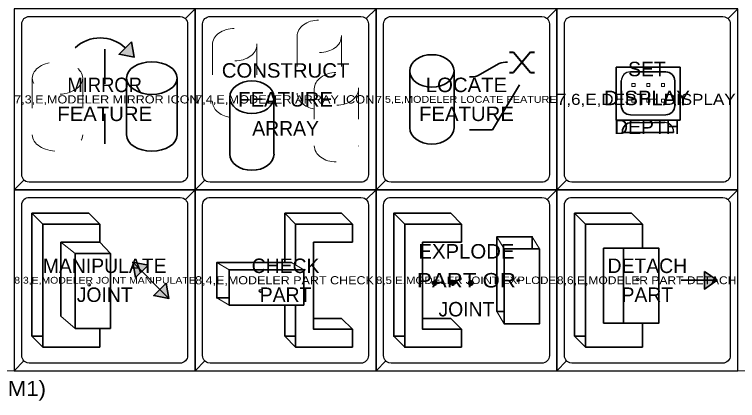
# Model space of a CAD drawing. Extents: x 95909.2 to 95923.3, y 90965 to 90971.2.
# Drawn here: x 95910.988 to 95913.386, y 90966.261 to 90967.542 of the extents above; entities that cross this region are included whole.
import ezdxf
from ezdxf.enums import TextEntityAlignment as Align

# ---------------------------------------------------------------- set-up
doc = ezdxf.new("R2010")
doc.units = 0
doc.header["$LTSCALE"] = 0.019
doc.header["$PDMODE"] = 32
doc.header["$PDSIZE"] = 0.0095
doc.linetypes.add('LONG_DASH_SHORT_DASH', pattern=[9.9, 6, -1.2, 1.5, -1.2])
doc.linetypes.add('MEDIUM_DASHED', pattern=[4.5, 3, -1.5])
for name, color, linetype, lineweight in [('1', 7, 'Continuous', 25), ('10', 7, 'Continuous', 13), ('2', 7, 'Continuous', 25), ('3', 7, 'Continuous', 25), ('4', 7, 'Continuous', 25), ('6', 7, 'Continuous', 13), ('7', 7, 'Continuous', 35)]:
    doc.layers.add(name, color=color, linetype=linetype, lineweight=lineweight)
doc.layers.add('5', color=7, linetype='Continuous')
doc.layers.add('63', color=7, linetype='Continuous')

msp = doc.modelspace()

# ---------------------------------------------------------------- hatches: boundary and pattern name
at = {"layer": '6'}
for points in [[(95911.3759, 90967.4511), (95911.385, 90967.4006), (95911.3346, 90967.4101)], [(95911.3893, 90966.6696), (95911.3799, 90966.7202), (95911.4305, 90966.7108)], [(95913.2761, 90966.6893), (95913.3184, 90966.6603), (95913.2761, 90966.6311)], [(95911.4905, 90966.6508), (95911.4998, 90966.6003), (95911.4493, 90966.6096)], [(95912.3813, 90966.65733, 1), (95912.3813, 90966.64533, 1)], [(95912.44103, 90966.65733, 1), (95912.44103, 90966.64533, 1)], [(95912.5013, 90966.65733, 1), (95912.5013, 90966.64533, 1)]]:
    msp.add_hatch(color=256, dxfattribs=at).paths.add_polyline_path(points)

# ---------------------------------------------------------------- linework, layer by layer
at = {"layer": '1'}
for points in [[(95910.9868, 90966.9603), (95911.5868, 90966.9603), (95911.5868, 90967.5603), (95910.9868, 90967.5603)], [(95911.5868, 90966.9603), (95912.1868, 90966.9603), (95912.1868, 90967.5603), (95911.5868, 90967.5603)], [(95912.1868, 90966.9603), (95912.7868, 90966.9603), (95912.7868, 90967.5603), (95912.1868, 90967.5603)], [(95912.7868, 90966.9603), (95913.3868, 90966.9603), (95913.3868, 90967.5603), (95912.7868, 90967.5603)], [(95910.9868, 90966.3603), (95911.5868, 90966.3603), (95911.5868, 90966.9603), (95910.9868, 90966.9603)], [(95911.5868, 90966.3603), (95912.1868, 90966.3603), (95912.1868, 90966.9603), (95911.5868, 90966.9603)], [(95912.1868, 90966.3603), (95912.7868, 90966.3603), (95912.7868, 90966.9603), (95912.1868, 90966.9603)], [(95912.7868, 90966.3603), (95913.3868, 90966.3603), (95913.3868, 90966.9603), (95912.7868, 90966.9603)]]:
    msp.add_lwpolyline(points, close=True, dxfattribs=at)
at = {"layer": '10'}
msp.add_lwpolyline([(95909.7868, 90971.1603), (95915.7868, 90971.1603), (95915.7868, 90966.3603), (95909.7868, 90966.3603)], close=True, dxfattribs=at)
at = {"layer": '2'}
for points in [[(95910.9868, 90966.9603), (95911.5868, 90966.9603), (95911.5868, 90967.5603), (95910.9868, 90967.5603)], [(95911.5868, 90966.9603), (95912.1868, 90966.9603), (95912.1868, 90967.5603), (95911.5868, 90967.5603)], [(95912.1868, 90966.9603), (95912.7868, 90966.9603), (95912.7868, 90967.5603), (95912.1868, 90967.5603)], [(95912.7868, 90966.9603), (95913.3868, 90966.9603), (95913.3868, 90967.5603), (95912.7868, 90967.5603)], [(95910.9868, 90966.3603), (95911.5868, 90966.3603), (95911.5868, 90966.9603), (95910.9868, 90966.9603)], [(95911.5868, 90966.3603), (95912.1868, 90966.3603), (95912.1868, 90966.9603), (95911.5868, 90966.9603)], [(95912.1868, 90966.3603), (95912.7868, 90966.3603), (95912.7868, 90966.9603), (95912.1868, 90966.9603)], [(95912.7868, 90966.3603), (95913.3868, 90966.3603), (95913.3868, 90966.9603), (95912.7868, 90966.9603)]]:
    msp.add_lwpolyline(points, close=True, dxfattribs=at)
at = {"layer": '3'}
for points in [[(95911.5868, 90967.5603), (95910.9868, 90967.5603), (95910.9868, 90966.9603), (95911.0191, 90966.9926), (95911.016, 90966.9964), (95911.0137, 90967.0007), (95911.0123, 90967.0054), (95911.0118, 90967.0103), (95911.0118, 90967.5103), (95911.0123, 90967.5152), (95911.0137, 90967.5199), (95911.016, 90967.5242), (95911.0191, 90967.528), (95911.0191, 90967.528), (95911.0229, 90967.5311), (95911.0272, 90967.5334), (95911.0319, 90967.5348), (95911.0368, 90967.5353), (95911.5368, 90967.5353), (95911.5441, 90967.5342), (95911.5486, 90967.5323), (95911.5527, 90967.5296), (95911.5545, 90967.528)], [(95912.1868, 90967.5603), (95911.5868, 90967.5603), (95911.5868, 90966.9603), (95911.6191, 90966.9926), (95911.616, 90966.9964), (95911.6137, 90967.0007), (95911.6123, 90967.0054), (95911.6118, 90967.0103), (95911.6118, 90967.5103), (95911.6123, 90967.5152), (95911.6137, 90967.5199), (95911.616, 90967.5242), (95911.6191, 90967.528), (95911.6191, 90967.528), (95911.6229, 90967.5311), (95911.6272, 90967.5334), (95911.6319, 90967.5348), (95911.6368, 90967.5353), (95912.1368, 90967.5353), (95912.1441, 90967.5342), (95912.1486, 90967.5323), (95912.1527, 90967.5296), (95912.1545, 90967.528)], [(95912.7868, 90967.5603), (95912.1868, 90967.5603), (95912.1868, 90966.9603), (95912.2191, 90966.9926), (95912.216, 90966.9964), (95912.2137, 90967.0007), (95912.2123, 90967.0054), (95912.2118, 90967.0103), (95912.2118, 90967.5103), (95912.2123, 90967.5152), (95912.2137, 90967.5199), (95912.216, 90967.5242), (95912.2191, 90967.528), (95912.2191, 90967.528), (95912.2229, 90967.5311), (95912.2272, 90967.5334), (95912.2319, 90967.5348), (95912.2368, 90967.5353), (95912.7368, 90967.5353), (95912.7441, 90967.5342), (95912.7486, 90967.5323), (95912.7527, 90967.5296), (95912.7545, 90967.528)], [(95913.3868, 90967.5603), (95912.7868, 90967.5603), (95912.7868, 90966.9603), (95912.8191, 90966.9926), (95912.816, 90966.9964), (95912.8137, 90967.0007), (95912.8123, 90967.0054), (95912.8118, 90967.0103), (95912.8118, 90967.5103), (95912.8123, 90967.5152), (95912.8137, 90967.5199), (95912.816, 90967.5242), (95912.8191, 90967.528), (95912.8191, 90967.528), (95912.8229, 90967.5311), (95912.8272, 90967.5334), (95912.8319, 90967.5348), (95912.8368, 90967.5353), (95913.3368, 90967.5353), (95913.3441, 90967.5342), (95913.3486, 90967.5323), (95913.3527, 90967.5296), (95913.3545, 90967.528)], [(95911.5868, 90966.9603), (95910.9868, 90966.9603), (95910.9868, 90966.3603), (95911.0191, 90966.3926), (95911.016, 90966.3964), (95911.0137, 90966.4007), (95911.0123, 90966.4054), (95911.0118, 90966.4103), (95911.0118, 90966.9103), (95911.0123, 90966.9152), (95911.0137, 90966.9199), (95911.016, 90966.9242), (95911.0191, 90966.928), (95911.0191, 90966.928), (95911.0229, 90966.9311), (95911.0272, 90966.9334), (95911.0319, 90966.9348), (95911.0368, 90966.9353), (95911.5368, 90966.9353), (95911.5441, 90966.9342), (95911.5486, 90966.9323), (95911.5527, 90966.9296), (95911.5545, 90966.928)], [(95912.1868, 90966.9603), (95911.5868, 90966.9603), (95911.5868, 90966.3603), (95911.6191, 90966.3926), (95911.616, 90966.3964), (95911.6137, 90966.4007), (95911.6123, 90966.4054), (95911.6118, 90966.4103), (95911.6118, 90966.9103), (95911.6123, 90966.9152), (95911.6137, 90966.9199), (95911.616, 90966.9242), (95911.6191, 90966.928), (95911.6191, 90966.928), (95911.6229, 90966.9311), (95911.6272, 90966.9334), (95911.6319, 90966.9348), (95911.6368, 90966.9353), (95912.1368, 90966.9353), (95912.1441, 90966.9342), (95912.1486, 90966.9323), (95912.1527, 90966.9296), (95912.1545, 90966.928)], [(95912.7868, 90966.9603), (95912.1868, 90966.9603), (95912.1868, 90966.3603), (95912.2191, 90966.3926), (95912.216, 90966.3964), (95912.2137, 90966.4007), (95912.2123, 90966.4054), (95912.2118, 90966.4103), (95912.2118, 90966.9103), (95912.2123, 90966.9152), (95912.2137, 90966.9199), (95912.216, 90966.9242), (95912.2191, 90966.928), (95912.2191, 90966.928), (95912.2229, 90966.9311), (95912.2272, 90966.9334), (95912.2319, 90966.9348), (95912.2368, 90966.9353), (95912.7368, 90966.9353), (95912.7441, 90966.9342), (95912.7486, 90966.9323), (95912.7527, 90966.9296), (95912.7545, 90966.928)], [(95913.3868, 90966.9603), (95912.7868, 90966.9603), (95912.7868, 90966.3603), (95912.8191, 90966.3926), (95912.816, 90966.3964), (95912.8137, 90966.4007), (95912.8123, 90966.4054), (95912.8118, 90966.4103), (95912.8118, 90966.9103), (95912.8123, 90966.9152), (95912.8137, 90966.9199), (95912.816, 90966.9242), (95912.8191, 90966.928), (95912.8191, 90966.928), (95912.8229, 90966.9311), (95912.8272, 90966.9334), (95912.8319, 90966.9348), (95912.8368, 90966.9353), (95913.3368, 90966.9353), (95913.3441, 90966.9342), (95913.3486, 90966.9323), (95913.3527, 90966.9296), (95913.3545, 90966.928)]]:
    msp.add_lwpolyline(points, close=True, dxfattribs=at)
at = {"layer": '4'}
for points in [[(95910.9868, 90966.9603), (95911.5868, 90966.9603), (95911.5868, 90967.5603), (95911.5545, 90967.528), (95911.5576, 90967.5242), (95911.5599, 90967.5199), (95911.5613, 90967.5152), (95911.5618, 90967.5103), (95911.5618, 90967.0103), (95911.5613, 90967.0054), (95911.5599, 90967.0007), (95911.5576, 90966.9964), (95911.5545, 90966.9926), (95911.5545, 90966.9926), (95911.5507, 90966.9895), (95911.5464, 90966.9872), (95911.5417, 90966.9858), (95911.5368, 90966.9853), (95911.0368, 90966.9853), (95911.0295, 90966.9864), (95911.025, 90966.9883), (95911.0209, 90966.991), (95911.0191, 90966.9926)], [(95911.5868, 90966.9603), (95912.1868, 90966.9603), (95912.1868, 90967.5603), (95912.1545, 90967.528), (95912.1576, 90967.5242), (95912.1599, 90967.5199), (95912.1613, 90967.5152), (95912.1618, 90967.5103), (95912.1618, 90967.0103), (95912.1613, 90967.0054), (95912.1599, 90967.0007), (95912.1576, 90966.9964), (95912.1545, 90966.9926), (95912.1545, 90966.9926), (95912.1507, 90966.9895), (95912.1464, 90966.9872), (95912.1417, 90966.9858), (95912.1368, 90966.9853), (95911.6368, 90966.9853), (95911.6295, 90966.9864), (95911.625, 90966.9883), (95911.6209, 90966.991), (95911.6191, 90966.9926)], [(95912.1868, 90966.9603), (95912.7868, 90966.9603), (95912.7868, 90967.5603), (95912.7545, 90967.528), (95912.7576, 90967.5242), (95912.7599, 90967.5199), (95912.7613, 90967.5152), (95912.7618, 90967.5103), (95912.7618, 90967.0103), (95912.7613, 90967.0054), (95912.7599, 90967.0007), (95912.7576, 90966.9964), (95912.7545, 90966.9926), (95912.7545, 90966.9926), (95912.7507, 90966.9895), (95912.7464, 90966.9872), (95912.7417, 90966.9858), (95912.7368, 90966.9853), (95912.2368, 90966.9853), (95912.2295, 90966.9864), (95912.225, 90966.9883), (95912.2209, 90966.991), (95912.2191, 90966.9926)], [(95912.7868, 90966.9603), (95913.3868, 90966.9603), (95913.3868, 90967.5603), (95913.3545, 90967.528), (95913.3576, 90967.5242), (95913.3599, 90967.5199), (95913.3613, 90967.5152), (95913.3618, 90967.5103), (95913.3618, 90967.0103), (95913.3613, 90967.0054), (95913.3599, 90967.0007), (95913.3576, 90966.9964), (95913.3545, 90966.9926), (95913.3545, 90966.9926), (95913.3507, 90966.9895), (95913.3464, 90966.9872), (95913.3417, 90966.9858), (95913.3368, 90966.9853), (95912.8368, 90966.9853), (95912.8295, 90966.9864), (95912.825, 90966.9883), (95912.8209, 90966.991), (95912.8191, 90966.9926)], [(95910.9868, 90966.3603), (95911.5868, 90966.3603), (95911.5868, 90966.9603), (95911.5545, 90966.928), (95911.5576, 90966.9242), (95911.5599, 90966.9199), (95911.5613, 90966.9152), (95911.5618, 90966.9103), (95911.5618, 90966.4103), (95911.5613, 90966.4054), (95911.5599, 90966.4007), (95911.5576, 90966.3964), (95911.5545, 90966.3926), (95911.5545, 90966.3926), (95911.5507, 90966.3895), (95911.5464, 90966.3872), (95911.5417, 90966.3858), (95911.5368, 90966.3853), (95911.0368, 90966.3853), (95911.0295, 90966.3864), (95911.025, 90966.3883), (95911.0209, 90966.391), (95911.0191, 90966.3926)], [(95911.5868, 90966.3603), (95912.1868, 90966.3603), (95912.1868, 90966.9603), (95912.1545, 90966.928), (95912.1576, 90966.9242), (95912.1599, 90966.9199), (95912.1613, 90966.9152), (95912.1618, 90966.9103), (95912.1618, 90966.4103), (95912.1613, 90966.4054), (95912.1599, 90966.4007), (95912.1576, 90966.3964), (95912.1545, 90966.3926), (95912.1545, 90966.3926), (95912.1507, 90966.3895), (95912.1464, 90966.3872), (95912.1417, 90966.3858), (95912.1368, 90966.3853), (95911.6368, 90966.3853), (95911.6295, 90966.3864), (95911.625, 90966.3883), (95911.6209, 90966.391), (95911.6191, 90966.3926)], [(95912.1868, 90966.3603), (95912.7868, 90966.3603), (95912.7868, 90966.9603), (95912.7545, 90966.928), (95912.7576, 90966.9242), (95912.7599, 90966.9199), (95912.7613, 90966.9152), (95912.7618, 90966.9103), (95912.7618, 90966.4103), (95912.7613, 90966.4054), (95912.7599, 90966.4007), (95912.7576, 90966.3964), (95912.7545, 90966.3926), (95912.7545, 90966.3926), (95912.7507, 90966.3895), (95912.7464, 90966.3872), (95912.7417, 90966.3858), (95912.7368, 90966.3853), (95912.2368, 90966.3853), (95912.2295, 90966.3864), (95912.225, 90966.3883), (95912.2209, 90966.391), (95912.2191, 90966.3926)], [(95912.7868, 90966.3603), (95913.3868, 90966.3603), (95913.3868, 90966.9603), (95913.3545, 90966.928), (95913.3576, 90966.9242), (95913.3599, 90966.9199), (95913.3613, 90966.9152), (95913.3618, 90966.9103), (95913.3618, 90966.4103), (95913.3613, 90966.4054), (95913.3599, 90966.4007), (95913.3576, 90966.3964), (95913.3545, 90966.3926), (95913.3545, 90966.3926), (95913.3507, 90966.3895), (95913.3464, 90966.3872), (95913.3417, 90966.3858), (95913.3368, 90966.3853), (95912.8368, 90966.3853), (95912.8295, 90966.3864), (95912.825, 90966.3883), (95912.8209, 90966.391), (95912.8191, 90966.3926)]]:
    msp.add_lwpolyline(points, close=True, dxfattribs=at)
at = {"layer": '6', "linetype": 'MEDIUM_DASHED'}
for p, q in [((95911.9251, 90967.4693), (95911.9251, 90967.2809)), ((95912.0721, 90967.4693), (95912.0721, 90967.3477)), ((95911.6444, 90967.4416), (95911.6444, 90967.2532)), ((95911.7914, 90967.4416), (95911.7914, 90967.3201)), ((95911.0468, 90967.3307), (95911.0468, 90967.1423)), ((95911.2139, 90967.3307), (95911.2139, 90967.1423)), ((95911.9821, 90967.2951), (95911.9821, 90967.1066)), ((95912.1291, 90967.2951), (95912.1291, 90967.1066))]:
    msp.add_line(p, q, dxfattribs=at)
at = {"layer": '6', "linetype": 'LONG_DASH_SHORT_DASH', "lineweight": 35}
msp.add_line((95911.2868, 90967.4263), (95911.2868, 90967.0683), dxfattribs=at)
at = {"layer": '6', "lineweight": 40}
for p, q in [((95912.6296, 90967.4172), (95912.6431, 90967.4172)), ((95912.6431, 90967.4172), (95912.6988, 90967.3496)), ((95912.6988, 90967.4172), (95912.6431, 90967.3496)), ((95912.6988, 90967.4172), (95912.7122, 90967.4172)), ((95912.6296, 90967.3496), (95912.6431, 90967.3496)), ((95912.6988, 90967.3496), (95912.7122, 90967.3496))]:
    msp.add_line(p, q, dxfattribs=at)
at = {"layer": '6', "lineweight": 35}
for p, q in [((95912.5239, 90967.3388), (95912.5956, 90967.3793)), ((95912.2985, 90967.3545), (95912.2985, 90967.166)), ((95912.4455, 90967.3545), (95912.4455, 90967.166)), ((95913.1479, 90967.3513), (95913.0304, 90967.3513)), ((95911.3597, 90967.3307), (95911.3597, 90967.1423)), ((95911.5268, 90967.3307), (95911.5268, 90967.1423)), ((95913.0004, 90967.3213), (95913.0004, 90967.2389)), ((95913.1779, 90967.2389), (95913.1779, 90967.3213)), ((95912.5731, 90967.159), (95912.6624, 90967.3086)), ((95911.7014, 90967.2674), (95911.7014, 90967.0789)), ((95911.8484, 90967.2674), (95911.8484, 90967.0789)), ((95912.5731, 90967.159), (95912.4966, 90967.159)), ((95913.174, 90967.1504), (95913.0043, 90967.1504)), ((95912.0727, 90966.8824), (95911.8839, 90966.8824)), ((95911.8839, 90966.8824), (95911.8839, 90966.7188)), ((95911.2707, 90966.846), (95911.2707, 90966.7866)), ((95912.1091, 90966.846), (95911.9202, 90966.846)), ((95911.9202, 90966.846), (95911.9202, 90966.7112)), ((95912.1091, 90966.846), (95912.1091, 90966.7866)), ((95912.4707, 90966.846), (95912.4707, 90966.7866)), ((95913.0707, 90966.846), (95913.0707, 90966.7662)), ((95913.0079, 90966.7662), (95912.9414, 90966.7662)), ((95911.4998, 90966.6003), (95911.3799, 90966.7202)), ((95913.199, 90966.6603), (95913.3184, 90966.6603)), ((95911.8839, 90966.5781), (95911.8839, 90966.4744)), ((95911.9202, 90966.5781), (95911.9202, 90966.438)), ((95912.5879, 90966.5566), (95912.6114, 90966.5566)), ((95911.9797, 90966.5339), (95912.0727, 90966.5339)), ((95912.3414, 90966.5339), (95912.4345, 90966.5339)), ((95911.2707, 90966.438), (95911.2707, 90966.5003)), ((95913.0707, 90966.438), (95913.0707, 90966.518)), ((95912.1091, 90966.438), (95912.1091, 90966.4976)), ((95912.4707, 90966.438), (95912.4707, 90966.4976)), ((95911.8839, 90966.4744), (95911.9202, 90966.4744)), ((95911.9202, 90966.438), (95912.1091, 90966.438))]:
    msp.add_line(p, q, dxfattribs=at)
at = {"layer": '6', "lineweight": 25}
for p, q in [((95913.0304, 90967.2089), (95913.1479, 90967.2089)), ((95913.0343, 90967.1835), (95913.144, 90967.1835)), ((95913.0043, 90967.1504), (95913.0043, 90967.1535)), ((95913.174, 90967.1535), (95913.174, 90967.1504))]:
    msp.add_line(p, q, dxfattribs=at)
at = {"layer": '6'}
for p, q in [((95911.0819, 90966.846), (95911.0456, 90966.8824)), ((95911.2707, 90966.846), (95911.2345, 90966.8824)), ((95911.9202, 90966.846), (95911.8839, 90966.8824)), ((95912.1091, 90966.846), (95912.0727, 90966.8824)), ((95912.2819, 90966.846), (95912.2456, 90966.8824)), ((95912.4707, 90966.846), (95912.4345, 90966.8824)), ((95912.8819, 90966.846), (95912.8456, 90966.8824)), ((95913.0707, 90966.846), (95913.0345, 90966.8824)), ((95912.6114, 90966.764), (95912.5879, 90966.8048)), ((95912.7286, 90966.764), (95912.7051, 90966.8048)), ((95911.1885, 90966.7486), (95911.1414, 90966.7866)), ((95911.3058, 90966.7486), (95911.2707, 90966.7866)), ((95911.6995, 90966.6953), (95911.6587, 90966.7188)), ((95911.9477, 90966.6953), (95911.9069, 90966.7188)), ((95911.6995, 90966.5781), (95911.6587, 90966.6016)), ((95912.6114, 90966.5157), (95912.5879, 90966.5566)), ((95911.1885, 90966.5003), (95911.1414, 90966.5412)), ((95912.1091, 90966.4976), (95912.0727, 90966.5339)), ((95912.4707, 90966.4976), (95912.4345, 90966.5339)), ((95911.0819, 90966.438), (95911.0456, 90966.4744)), ((95911.9202, 90966.438), (95911.8839, 90966.4744)), ((95912.2819, 90966.438), (95912.2456, 90966.4744)), ((95912.8819, 90966.438), (95912.8456, 90966.4744))]:
    msp.add_line(p, q, dxfattribs=at)
at = {"layer": '6', "lineweight": 35}
for points in [[(95911.3759, 90967.4511), (95911.385, 90967.4006), (95911.3346, 90967.4101)], [(95912.9829, 90967.3669), (95913.1955, 90967.3669), (95913.1955, 90967.1913), (95912.9829, 90967.1913)], [(95912.6114, 90966.5157), (95912.7286, 90966.5157), (95912.7286, 90966.764), (95912.6114, 90966.764)], [(95913.0079, 90966.518), (95913.125, 90966.518), (95913.125, 90966.7662), (95913.0079, 90966.7662)], [(95911.1885, 90966.5003), (95911.3058, 90966.5003), (95911.3058, 90966.7486), (95911.1885, 90966.7486)], [(95911.3893, 90966.6696), (95911.3799, 90966.7202), (95911.4305, 90966.7108)], [(95911.9477, 90966.5781), (95911.9477, 90966.6953), (95911.6995, 90966.6953), (95911.6995, 90966.5781)], [(95913.2761, 90966.6893), (95913.3184, 90966.6603), (95913.2761, 90966.6311)], [(95911.4905, 90966.6508), (95911.4998, 90966.6003), (95911.4493, 90966.6096)]]:
    msp.add_lwpolyline(points, close=True, dxfattribs=at)
at = {"layer": '6'}
for points in [[(95913.0359, 90967.3026), (95913.0459, 90967.3026), (95913.0459, 90967.3126), (95913.0359, 90967.3126)], [(95913.0847, 90967.3026), (95913.0947, 90967.3026), (95913.0947, 90967.3126), (95913.0847, 90967.3126)], [(95913.1335, 90967.3026), (95913.1435, 90967.3026), (95913.1435, 90967.3126), (95913.1335, 90967.3126)], [(95913.0359, 90967.2512), (95913.0459, 90967.2512), (95913.0459, 90967.2612), (95913.0359, 90967.2612)], [(95913.0847, 90967.2512), (95913.0947, 90967.2512), (95913.0947, 90967.2612), (95913.0847, 90967.2612)], [(95913.1335, 90967.2512), (95913.1435, 90967.2512), (95913.1435, 90967.2612), (95913.1335, 90967.2612)]]:
    msp.add_lwpolyline(points, close=True, dxfattribs=at)
at = {"layer": '6', "lineweight": 35}
for points in [[(95911.2345, 90966.8824), (95911.0456, 90966.8824), (95911.0456, 90966.4744), (95911.0819, 90966.4744)], [(95912.4345, 90966.8824), (95912.2456, 90966.8824), (95912.2456, 90966.4744), (95912.2819, 90966.4744)], [(95913.0345, 90966.8824), (95912.8456, 90966.8824), (95912.8456, 90966.4744), (95912.8819, 90966.4744)], [(95911.2707, 90966.846), (95911.0819, 90966.846), (95911.0819, 90966.438), (95911.2707, 90966.438)], [(95912.4707, 90966.846), (95912.2819, 90966.846), (95912.2819, 90966.438), (95912.4707, 90966.438)], [(95913.0707, 90966.846), (95912.8819, 90966.846), (95912.8819, 90966.438), (95913.0707, 90966.438)], [(95912.7051, 90966.764), (95912.7051, 90966.8048), (95912.5879, 90966.8048), (95912.5879, 90966.5566)], [(95911.2707, 90966.7866), (95911.1414, 90966.7866), (95911.1414, 90966.5412)], [(95912.1091, 90966.7866), (95911.9797, 90966.7866), (95911.9797, 90966.4976), (95912.1091, 90966.4976)], [(95912.4707, 90966.7866), (95912.3414, 90966.7866), (95912.3414, 90966.4976), (95912.4707, 90966.4976)], [(95912.9414, 90966.7662), (95912.9414, 90966.518), (95913.0079, 90966.518)], [(95911.6995, 90966.6016), (95911.6587, 90966.6016), (95911.6587, 90966.7188), (95911.9069, 90966.7188)]]:
    msp.add_lwpolyline(points, dxfattribs=at)
at = {"layer": '6', "lineweight": 53}
for centre in [(95912.3813, 90966.65133), (95912.44103, 90966.65133), (95912.5013, 90966.65133)]:
    msp.add_circle(centre, 0.006, dxfattribs=at)
at = {"layer": '6', "lineweight": 35}
for centre, radius, start, end in [((95911.27183, 90967.3443), 0.12, 46.00293, 133.99745), ((95912.6181, 90967.32242), 0.06117, 85.49914, 111.58292), ((95912.5014, 90967.39568), 0.06117, 265.49914, 291.58292), ((95913.1479, 90967.3213), 0.03, 0, 90), ((95913.0304, 90967.2389), 0.03, 180, 270), ((95913.1479, 90967.2389), 0.03, 270, 0), ((95913.0343, 90967.1535), 0.03, 90, 180)]:
    msp.add_arc(centre, radius, start, end, dxfattribs=at)
at = {"layer": '6', "lineweight": 25}
for centre, start, end in [((95913.0304, 90967.3213), 90, 180), ((95913.144, 90967.1535), 0, 90)]:
    msp.add_arc(centre, 0.03, start, end, dxfattribs=at)
at = {"layer": '6', "linetype": 'MEDIUM_DASHED'}
for centre, major_axis, ratio in [((95911.99855, 90967.46938), (0.07351, 0), 0.734818), ((95911.71793, 90967.44167), (0.07351, 0), 0.734818), ((95911.13028, 90967.33079), (0.08353, 0), 0.64664), ((95912.05558, 90967.29509), (0.07351, 0), 0.734818)]:
    msp.add_ellipse(centre, major_axis=major_axis, ratio=ratio, dxfattribs=at)
at = {"layer": '6', "lineweight": 35}
for centre, major_axis, ratio in [((95912.37206, 90967.35448), (0.07351, 0), 0.734818), ((95911.44324, 90967.33079), (-0.08353, 0), 0.64664), ((95911.77496, 90967.26738), (0.07351, 0), 0.734818)]:
    msp.add_ellipse(centre, major_axis=major_axis, ratio=ratio, dxfattribs=at)
at = {"layer": '6', "linetype": 'MEDIUM_DASHED'}
for centre, major_axis, ratio, end_param in [((95911.99855, 90967.28093), (0.07351, 0), 0.734818, 4.4862883), ((95911.71793, 90967.25322), (0.07351, 0), 0.734818, 4.4862883), ((95911.13028, 90967.14234), (0.08353, 0), 0.64664, 6.2831028), ((95912.05558, 90967.10664), (0.07351, 0), 0.734818, 6.2831028)]:
    msp.add_ellipse(centre, major_axis=major_axis, ratio=ratio, start_param=3.1416618, end_param=end_param, dxfattribs=at)
at = {"layer": '6', "lineweight": 35}
for centre, major_axis, ratio, start_param, end_param in [((95912.37206, 90967.16603), (0.07351, 0), 0.734818, 3.1416618, 6.2831028), ((95911.44324, 90967.14234), (-0.08353, 0), 0.64664, 0.0000825, 3.1415235), ((95911.77496, 90967.07893), (0.07351, 0), 0.734818, 3.1416618, 6.2831028)]:
    msp.add_ellipse(centre, major_axis=major_axis, ratio=ratio, start_param=start_param, end_param=end_param, dxfattribs=at)
at = {"layer": '6'}
for p in [(95913.0547, 90966.6626), (95911.2355, 90966.6449), (95912.6582, 90966.6603), (95911.8032, 90966.6249)]:
    msp.add_point(p, dxfattribs=at)

# ---------------------------------------------------------------- texts
at = {"layer": '5'}
for s, width, p in [('CONSTRUCT', 1.05, (95911.8868, 90967.3323)), ('MIRROR', 0.95, (95911.2868, 90967.2843)), ('LOCATE', 1.05, (95912.4868, 90967.2843)), ('FEATURE', 1.05, (95911.8868, 90967.2363)), ('DISPLAY', 1.05, (95913.08545, 90967.2409)), ('FEATURE', 1.05, (95911.2868, 90967.1883)), ('FEATURE', 1.05, (95912.4868, 90967.1883)), ('EXPLODE', 1.05, (95912.48675, 90966.7323)), ('PART OR', 1.15, (95912.4868, 90966.6363))]:
    msp.add_text(s, height=0.048, dxfattribs=dict(at, width=width)).set_placement(p, align=Align.CENTER)
for s, p in [('SET', (95913.0854, 90967.3369)), ('ARRAY', (95911.88685, 90967.1403)), ('DEPTH', (95913.0854, 90967.1449)), ('MANIPULATE', (95911.28675, 90966.6843)), ('CHECK', (95911.8868, 90966.6843)), ('DETACH', (95913.0868, 90966.6843)), ('JOINT', (95911.2868, 90966.5883)), ('PART', (95911.8868, 90966.5883)), ('PART', (95913.0868, 90966.5883)), ('JOINT', (95912.4868, 90966.5403))]:
    msp.add_text(s, height=0.048, dxfattribs=at).set_placement(p, align=Align.CENTER)
at = {"layer": '63', "width": 1.15}
for s, height, p in [('7,3,E,MODELER MIRROR ICON', 0.0271, (95910.9868, 90967.2467)), ('7,4,E,MODELER ARRAY ICON', 0.0275, (95911.5868, 90967.2465)), ('7,5,E,MODELER LOCATE FEATURE', 0.0232, (95912.1868, 90967.2487)), ('7,6,E,DEPTH DISPLAY', 0.0367, (95912.7868, 90967.2419)), ('8,3,E,MODELER JOINT MANIPULATE', 0.0225, (95910.9868, 90966.6491)), ('8,4,E,MODELER PART CHECK', 0.027, (95911.5868, 90966.6468)), ('8,5,E,MODELER JOINT EXPLODE', 0.0247, (95912.1868, 90966.6479)), ('8,6,E,MODELER PART DETACH', 0.026, (95912.7868, 90966.6473))]:
    msp.add_text(s, height=height, dxfattribs=at).set_placement(p)
at = {"layer": '7', "width": 1.1}
msp.add_text('ORIGIN (AM=55MOD,M1)', height=0.05, dxfattribs=at).set_placement((95910.66205, 90966.2764), align=Align.CENTER)

doc.saveas('drawing.dxf')
